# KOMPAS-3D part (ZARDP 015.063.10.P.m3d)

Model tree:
1. Плоскость XY
2. Плоскость ZX
3. Плоскость ZY
4. Ось X
5. Ось Y
6. Ось Z
7. Начало координат
8. Смещенная плоскость:2
     Расстояние = 60
9. Булева операция:3
10. Булева операция:4
